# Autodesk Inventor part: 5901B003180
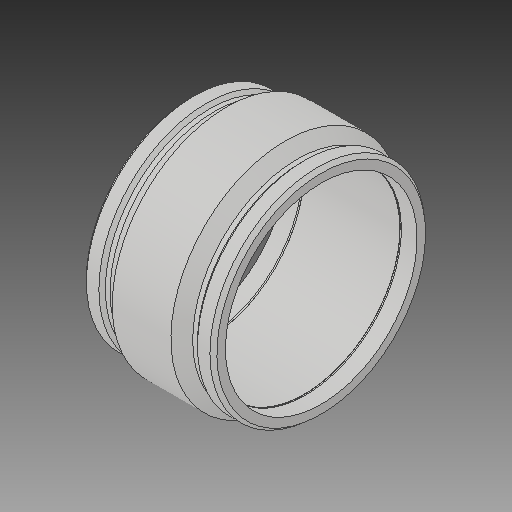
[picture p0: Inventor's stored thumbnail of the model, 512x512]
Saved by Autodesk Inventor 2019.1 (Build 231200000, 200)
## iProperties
Created: 2017-06
Part Number: 5901B003180
Material: Generic
Description: PLASSON IPS COUPLER 18''
Document SubType Name: Modeling
Designer: KIM
Mass: 8622.19 g
Surface Area: 6772.47 cm^2
Volume: 8622.19 cm^3
Density: 1 g/cm^3
Appearance: Default
Author: KIM
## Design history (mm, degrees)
derived "5901B.ipt"
feature "Solid1::5901B.ipt"
tag "TaggingFeature1"
body "Solid1"
other parameters: "d0" = 309.88, "d1" = 455.1, "d2" = 543.56, "d3" = 154.94, "d4" = 77.47, "d5" = 489.204, "d6" = 364.08, "d7" = 455.1, "d8" = 168 deg, "d10" = 61.976, "d11" = 20.65867, "d13" = 309.88, "d14" = 17.6296, "d18" = 455.1, "d19" = 3.52592, "d20" = 168 deg, "d22" = 510.9464, "d23" = 543.56, "d24" = 495.61801, "d25" = 135 deg, "d26" = 139.446, "d27" = 135 deg, "d29" = 254, "d30" = 15, "d31" = 108.458, "d34" = 5 deg, "d35" = 15, "d39" = 5 deg, "d41" = 4, "d42" = 14, "d43" = 0, "d45" = 4, "d46" = 14, "d47" = 0, "d48" = 3, "d49" = 0, "d50" = 3, "d51" = 0, "d52" = 44.9326, "d53" = 11.23315, "d55" = 154.94, "d_" = 455.1, "L_" = 309.88, "L_1" = 154.94, "D_" = 543.56, "A_" = 254, "d_2" = 12, "B_" = 254
